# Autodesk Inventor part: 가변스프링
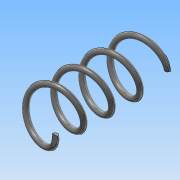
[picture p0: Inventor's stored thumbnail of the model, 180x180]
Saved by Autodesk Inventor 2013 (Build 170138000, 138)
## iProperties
Created: 2015-09
Part Number: 가변스프링
Material: 강철, 탄소
Document SubType Name: Modeling
Designer: Administrator
Density: 7.87 g/cm^3
Mass: 4.92088 g
Surface Area: 12.7468 cm^2
Volume: 0.625271 cm^3
Author: Administrator
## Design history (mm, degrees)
sketch "스케치1"
  geometry: L1 (0, 0)-(0, 42); L2 (0, 0)-(8, 0); L3 (0, 42)-(8, 42); C1 r 1 at (8, 0)
  constraints: 6 end point, 1 centre point, 1 horizontal alignment, 1 parallel, 1 perpendicular, 1 vertical
  dimensions: "d0" = 42 distance of L1.start L1.end (derived); "d1" = 2 diameter of C1; "d2" = 16 diameter of L2.end L1
feature "코일1" sketch "스케치1" pitch "d3" = 10; turns "d5" = 4; dims "d4" = 42 (= d0), "d6" = 0, angle "d7" = 90 deg, angle "d8" = 90 deg, "d9" = 0, "d10" = 0
sketch "스케치2"
  geometry: L1 (42, 10)-(0, 10); L2 (0, 10)-(0, -10); L3 (0, -10)-(42, -10); L4 (42, -10)-(42, 10); 2 further points
  constraints: 8 end point, 2 parallel, 1 coincident, 1 horizontal, 1 midpoint, 1 perpendicular
  dimensions: "d11" = 20 distance between parallel lines of L3 L1; "d13" = 42 distance of L1.start L1.end (derived)
extrude "돌출1" sketch "스케치2" stored distance "d14" = 20; taper "d15" = 0 deg
node "솔리드1"
